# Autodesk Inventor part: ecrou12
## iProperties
Shininess: 21.0
Length Units: 11269
Angle Units: 11279
Time Units: 11290
Mass Units: 11283
Length Display Precision: 3
Angle Display Precision: 2
Compacted: True
Created: 2001-12
Part Number: ecrou12
Material: Par défaut
Document SubType Name: Modélisation
Designer: pichon
Density: 0.0
Volumn: 0.0
Area: 0.0
PropertySet Name: Model Information
Control State: 0
Master: False
Checked Out: False
Author: pichon
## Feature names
1. Corps dérivé1 [Tagging]
